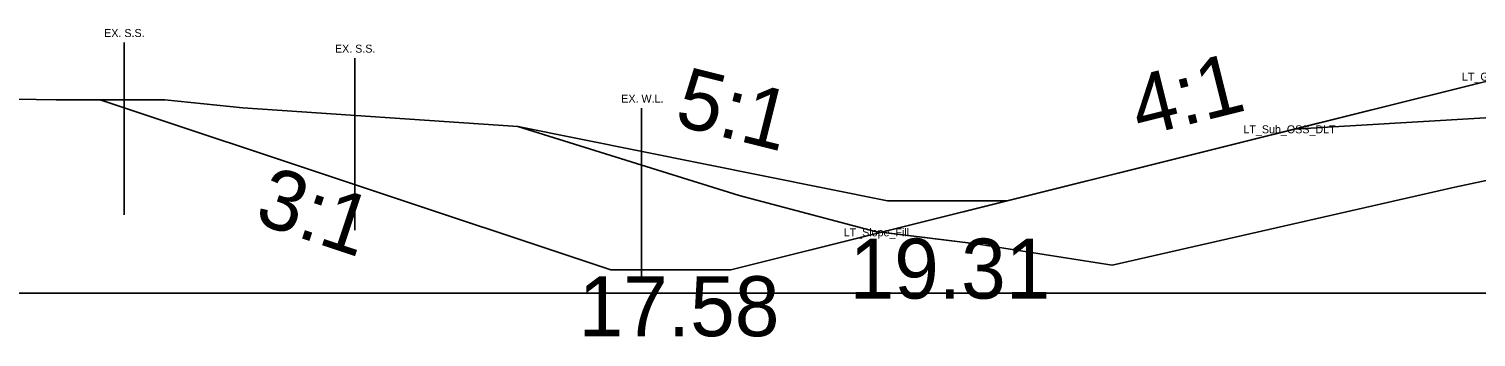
# Model space of a CAD drawing. Extents: x 2177029 to 2201446, y 59897 to 78390.
# Drawn here: x 2200127.85 to 2200164.01, y 67406.21 to 67413.92 of the extents above; entities that cross this region are included whole.
import ezdxf

# ---------------------------------------------------------------- set-up
doc = ezdxf.new("R2010")
doc.units = 0
for name, color, linetype in [('Exist Cross Section Cell', 7, 'Continuous'), ('Exist PHM Roadway Shape', 7, 'Continuous'), ('Exist XS Ground Line', 7, 'Continuous'), ('Old_Level_1', 7, 'Continuous'), ('Prop CMT Guardrail Widen Shoulder', 7, 'Continuous'), ('Prop CMT Pvmt Course 3', 7, 'Continuous'), ('Prop CMT Pvmt Surface Shoulder', 7, 'Continuous'), ('Prop CMT Top Wall Envelope', 7, 'Continuous'), ('Prop Hatching', 7, 'Continuous'), ('Prop XS Earthwork Shape', 7, 'Continuous'), ('Prop XS Side Slope Text', 7, 'Continuous')]:
    doc.layers.add(name, color=color, linetype=linetype)

msp = doc.modelspace()

# ---------------------------------------------------------------- linework, layer by layer
at = {"layer": 'Exist Cross Section Cell'}
msp.add_line((2200042.732, 67407.31), (2200242.732, 67407.31), dxfattribs=at)
at = {"layer": 'Exist XS Ground Line'}
msp.add_lwpolyline([(2200117.948, 67412.321), (2200128.531, 67412.142), (2200131.247, 67412.145), (2200133.191, 67411.949), (2200140.069, 67411.477), (2200145.594, 67409.756), (2200148.996, 67408.853), (2200151.52, 67408.544), (2200154.92, 67408.013), (2200163.481, 67409.957), (2200174.258, 67412.255)], dxfattribs=at)
at = {"layer": 'Old_Level_1'}
for p, q in [((2200140.069, 67411.477), (2200149.302, 67409.619)), ((2200149.302, 67409.619), (2200152.302, 67409.619))]:
    msp.add_line(p, q, dxfattribs=at)
at = {"layer": 'Prop CMT Pvmt Course 3'}
msp.add_lwpolyline([(2200165.658, 67411.78), (2200159.459, 67411.408)], dxfattribs=at)
at = {"layer": 'Prop CMT Pvmt Surface Shoulder'}
msp.add_line((2200143.157, 67411.939), (2200143.157, 67407.631), dxfattribs=at)
at = {"layer": 'Prop Hatching'}
for p, q in [((2200142.386, 67407.89), (2200129.627, 67412.143)), ((2200145.386, 67407.89), (2200142.386, 67407.89))]:
    msp.add_line(p, q, dxfattribs=at)
msp.add_lwpolyline([(2200166.721, 67412.844), (2200164.722, 67412.724), (2200145.386, 67407.89)], dxfattribs=at)
at = {"layer": 'Prop XS Earthwork Shape'}
for p, q in [((2200130.226, 67413.58), (2200130.226, 67409.272)), ((2200135.994, 67413.19), (2200135.994, 67408.882))]:
    msp.add_line(p, q, dxfattribs=at)
at = {"layer": 'Prop XS Side Slope Text'}
msp.add_lwpolyline([(2200164.722, 67412.724), (2200159.458, 67411.408), (2200165.658, 67411.78)], dxfattribs=at)
for points in [[(2200142.386, 67407.89), (2200129.627, 67412.143), (2200131.247, 67412.145), (2200133.191, 67411.949), (2200140.069, 67411.477), (2200145.594, 67409.756), (2200148.996, 67408.853), (2200149.156, 67408.833), (2200145.386, 67407.89)], [(2200165.658, 67411.78), (2200159.458, 67411.408), (2200149.156, 67408.833), (2200151.52, 67408.544), (2200154.92, 67408.013), (2200163.481, 67409.957), (2200174.258, 67412.255), (2200175.074, 67412.345)]]:
    msp.add_lwpolyline(points, close=True, dxfattribs=at)

# ---------------------------------------------------------------- texts
at = {"layer": 'Exist PHM Roadway Shape'}
for s, p in [('LT_GS_OS_CTL', (2200163.659, 67412.624)), ('LT_Sub_OSS_DLT', (2200158.199, 67411.308)), ('LT_Slope_Fill', (2200148.209, 67408.732))]:
    msp.add_text(s, height=0.2, dxfattribs=at).set_placement(p)
at = {"layer": 'Old_Level_1'}
msp.add_text('5:1', height=1.5, rotation=345.9635, dxfattribs=at).set_placement((2200143.943, 67411.527))
msp.add_text('19.31', height=1.5, dxfattribs=at).set_placement((2200148.355, 67407.174))
at = {"layer": 'Prop CMT Guardrail Widen Shoulder'}
msp.add_text('4:1', height=1.5, rotation=14.0388, dxfattribs=at).set_placement((2200155.604, 67411.218))
at = {"layer": 'Prop CMT Pvmt Surface Shoulder'}
msp.add_text('EX. W.L.', height=0.2, dxfattribs=at).set_placement((2200142.651, 67412.074))
at = {"layer": 'Prop CMT Top Wall Envelope'}
msp.add_text('3:1', height=1.5, rotation=341.5651, dxfattribs=at).set_placement((2200133.444, 67409.087))
msp.add_text('17.58', height=1.5, dxfattribs=at).set_placement((2200141.584, 67406.233))
at = {"layer": 'Prop XS Earthwork Shape'}
for p in [(2200129.728, 67413.716), (2200135.496, 67413.325)]:
    msp.add_text('EX. S.S.', height=0.2, dxfattribs=at).set_placement(p)

doc.saveas('drawing.dxf')
